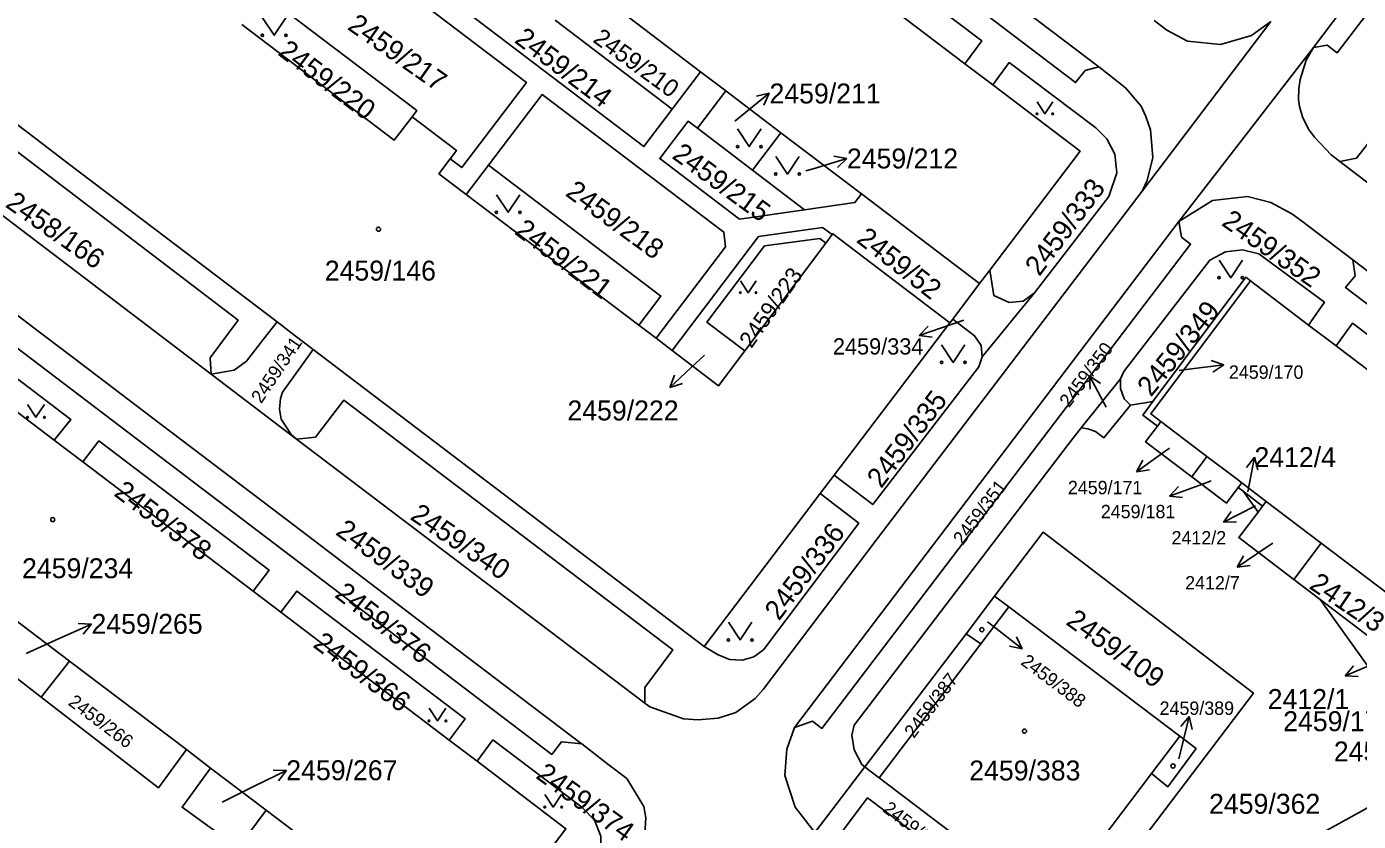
# Model space of a CAD drawing. Extents: x -606208 to -605570, y -1157873 to -1157573.
# Drawn here: x -605870.3 to -605756.7, y -1157700.9 to -1157633.1 of the extents above; entities that cross this region are included whole.
import ezdxf

# ---------------------------------------------------------------- set-up
doc = ezdxf.new("R2010")
doc.units = 0
doc.layers.add('Vrstva 62', color=7, linetype='Continuous')

msp = doc.modelspace()

# ---------------------------------------------------------------- linework, layer by layer
at = {"layer": 'Vrstva 62'}
for p, q in [((-605746.58, -1157616.44), (-605760.58, -1157634.9)), ((-605790.3, -1157636.28), (-605804.68, -1157625.36)), ((-605822.81, -1157629.39), (-605812.84, -1157636.96)), ((-605825.22, -1157632.57), (-605815.25, -1157640.15)), ((-605775.19, -1157647.15), (-605764.22, -1157632.67)), ((-605760.58, -1157634.9), (-605772.05, -1157649.74)), ((-605812.84, -1157636.96), (-605815.25, -1157640.15)), ((-605810.69, -1157638.6), (-605812.84, -1157636.96)), ((-605787.92, -1157638.08), (-605790.3, -1157636.28)), ((-605813.1, -1157641.78), (-605810.69, -1157638.6)), ((-605810.69, -1157638.6), (-605805.99, -1157642.16)), ((-605809.31, -1157640.69), (-605806.98, -1157638.8)), ((-605806.98, -1157638.8), (-605808.07, -1157639.04)), ((-605806.98, -1157638.8), (-605807.44, -1157639.82)), ((-605883.72, -1157640.58), (-605854.57, -1157662.74)), ((-605809.92, -1157641.18), (-605809.31, -1157640.69)), ((-605813.1, -1157641.78), (-605808.4, -1157645.35)), ((-605808.4, -1157645.35), (-605805.99, -1157642.16)), ((-605805.99, -1157642.16), (-605799.12, -1157647.38)), ((-605800.36, -1157644.35), (-605801.46, -1157644.17)), ((-605832.81, -1157647.44), (-605830.91, -1157644.93)), ((-605808.4, -1157645.35), (-605803.96, -1157648.73)), ((-605803.85, -1157645.42), (-605803.23, -1157645.23)), ((-605803.23, -1157645.23), (-605800.36, -1157644.35)), ((-605800.36, -1157644.35), (-605801.17, -1157645.12)), ((-605818.1, -1157658.58), (-605832.81, -1157647.44)), ((-605789.04, -1157655.03), (-605799.12, -1157647.38)), ((-605772.05, -1157649.74), (-605804.82, -1157692.87)), ((-605801.62, -1157650.85), (-605802.16, -1157651.57)), ((-605802.16, -1157651.57), (-605809.07, -1157660.76)), ((-605789.04, -1157655.03), (-605788.16, -1157653.87)), ((-605791.34, -1157658.06), (-605789.04, -1157655.03)), ((-605761, -1157658.57), (-605765.95, -1157654.78)), ((-605784.37, -1157655.81), (-605788.82, -1157661.28)), ((-605867.94, -1157668.37), (-605882.28, -1157657.48)), ((-605816.63, -1157659.69), (-605818.1, -1157658.58)), ((-605801.44, -1157671.35), (-605791.57, -1157658.36)), ((-605791.37, -1157658.47), (-605794.21, -1157659.45)), ((-605794.21, -1157659.45), (-605793.42, -1157658.65)), ((-605791.57, -1157658.36), (-605791.34, -1157658.06)), ((-605790.39, -1157658.14), (-605791.37, -1157658.47)), ((-605758.65, -1157660.32), (-605761, -1157658.57)), ((-605816.63, -1157659.69), (-605815.27, -1157660.72)), ((-605794.21, -1157659.45), (-605793.1, -1157659.59)), ((-605845.86, -1157660.64), (-605812.52, -1157685.95)), ((-605812.5, -1157661.13), (-605813.25, -1157661.82)), ((-605813.25, -1157661.82), (-605815.45, -1157663.87)), ((-605772.03, -1157662.43), (-605771.21, -1157662.32)), ((-605771.21, -1157662.32), (-605768.23, -1157661.95)), ((-605768.23, -1157661.95), (-605769.29, -1157661.58)), ((-605768.23, -1157661.95), (-605769.16, -1157662.57)), ((-605854.57, -1157662.74), (-605847.28, -1157668.28)), ((-605815.45, -1157663.87), (-605815.05, -1157662.82)), ((-605777.03, -1157663.14), (-605780.39, -1157667.33)), ((-605778.25, -1157665.55), (-605779.66, -1157662.9)), ((-605779.66, -1157662.9), (-605778.75, -1157663.55)), ((-605779.66, -1157662.9), (-605779.63, -1157664.02)), ((-605815.45, -1157663.87), (-605814.37, -1157663.55)), ((-605776.18, -1157665.39), (-605774.28, -1157665.09)), ((-605773.88, -1157667.18), (-605773.58, -1157666.78)), ((-605773.58, -1157666.78), (-605769.66, -1157669.76)), ((-605865.51, -1157670.21), (-605867.94, -1157668.37)), ((-605847.28, -1157668.28), (-605817.58, -1157690.8)), ((-605772.85, -1157669.04), (-605773.23, -1157669.32)), ((-605850.97, -1157681.25), (-605865.51, -1157670.21)), ((-605773.23, -1157669.32), (-605775.66, -1157671.08)), ((-605775.66, -1157671.08), (-605775.14, -1157670.09)), ((-605770.96, -1157671.49), (-605769.66, -1157669.76)), ((-605765.61, -1157669.82), (-605766.29, -1157670.71)), ((-605766.18, -1157672.77), (-605765.61, -1157669.82)), ((-605765.61, -1157669.82), (-605765.31, -1157670.9)), ((-605802.63, -1157672.93), (-605801.44, -1157671.35)), ((-605775.66, -1157671.08), (-605774.55, -1157670.9)), ((-605770.03, -1157672.11), (-605772.85, -1157673.14)), ((-605772.85, -1157673.14), (-605772.08, -1157672.32)), ((-605769.29, -1157671.84), (-605770.03, -1157672.11)), ((-605766.69, -1157672.01), (-605766.99, -1157672.41)), ((-605766.99, -1157672.41), (-605766.57, -1157672.73)), ((-605766.69, -1157672.01), (-605764.61, -1157673.59)), ((-605812.52, -1157685.95), (-605802.63, -1157672.93)), ((-605772.85, -1157673.14), (-605771.74, -1157673.26)), ((-605766.57, -1157672.73), (-605765.3, -1157674.51)), ((-605764.91, -1157673.99), (-605766.57, -1157672.73)), ((-605764.91, -1157673.99), (-605764.61, -1157673.59)), ((-605764.61, -1157673.59), (-605759.91, -1157677.16)), ((-605765.58, -1157673.99), (-605768.25, -1157675.35)), ((-605768.25, -1157675.35), (-605767.59, -1157674.45)), ((-605765.52, -1157673.96), (-605765.58, -1157673.99)), ((-605765.3, -1157674.51), (-605764.91, -1157673.99)), ((-605768.25, -1157675.35), (-605767.13, -1157675.34)), ((-605764.6, -1157677.52), (-605767.09, -1157679.2)), ((-605767.09, -1157679.2), (-605766.54, -1157678.22)), ((-605764.05, -1157677.15), (-605764.6, -1157677.52)), ((-605759.91, -1157677.16), (-605762.25, -1157680.24)), ((-605759.91, -1157677.16), (-605752.43, -1157682.83)), ((-605767.09, -1157679.2), (-605765.98, -1157679.05)), ((-605762.25, -1157680.24), (-605760, -1157681.95)), ((-605848.61, -1157683.04), (-605850.97, -1157681.25)), ((-605790.19, -1157684.87), (-605787.77, -1157681.67)), ((-605787.77, -1157681.67), (-605786.56, -1157682.59)), ((-605786.56, -1157682.59), (-605788.94, -1157685.73)), ((-605786.56, -1157682.59), (-605771.98, -1157693.61)), ((-605871.39, -1157683.59), (-605866.63, -1157687.2)), ((-605834.26, -1157693.94), (-605848.61, -1157683.04)), ((-605788.37, -1157683.85), (-605787.77, -1157684.31)), ((-605867.51, -1157685.27), (-605864.77, -1157684.05)), ((-605864.77, -1157684.05), (-605865.89, -1157684)), ((-605864.77, -1157684.05), (-605865.48, -1157684.91)), ((-605798.82, -1157696.23), (-605790.19, -1157684.87)), ((-605788.94, -1157685.73), (-605790.19, -1157684.87)), ((-605787.77, -1157684.31), (-605785.41, -1157686.16)), ((-605870.35, -1157686.55), (-605867.51, -1157685.27)), ((-605788.94, -1157685.73), (-605797.62, -1157697.15)), ((-605785.41, -1157686.16), (-605786.5, -1157685.94)), ((-605785.41, -1157686.16), (-605785.89, -1157685.15)), ((-605869.06, -1157690.28), (-605866.63, -1157687.2)), ((-605866.63, -1157687.2), (-605856.68, -1157694.75)), ((-605755.11, -1157687.29), (-605757.87, -1157688.46)), ((-605757.87, -1157688.46), (-605757.15, -1157687.61)), ((-605757.87, -1157688.46), (-605756.76, -1157688.53)), ((-605771.9, -1157694.85), (-605771.17, -1157691.94)), ((-605771.17, -1157691.94), (-605771.9, -1157692.79)), ((-605771.17, -1157691.94), (-605770.93, -1157693.03)), ((-605831.89, -1157695.74), (-605834.26, -1157693.94)), ((-605774.39, -1157696.8), (-605771.98, -1157693.61)), ((-605854.61, -1157696.32), (-605856.68, -1157694.75)), ((-605772.07, -1157695.53), (-605771.9, -1157694.85)), ((-605854.61, -1157696.32), (-605849.88, -1157699.91)), ((-605798.82, -1157696.23), (-605803.08, -1157701.83)), ((-605850.85, -1157697.84), (-605848.15, -1157696.52)), ((-605848.15, -1157696.52), (-605849.27, -1157696.51)), ((-605848.15, -1157696.52), (-605848.83, -1157697.41)), ((-605788.23, -1157704.27), (-605797.62, -1157697.15)), ((-605853.64, -1157699.22), (-605850.85, -1157697.84)), ((-605852.27, -1157703.13), (-605849.88, -1157699.91))]:
    msp.add_line(p, q, dxfattribs=at)
for points in [[(-605778.88, -1157636.54), (-605780.04, -1157636.85), (-605780.86, -1157637.89), (-605819.82, -1157608.27), (-605840.4, -1157592.63), (-605839.55, -1157591.51), (-605839.57, -1157590.41)], [(-605839.57, -1157590.41), (-605835.8, -1157593.29), (-605832.45, -1157595.85), (-605828.25, -1157599.04), (-605822.26, -1157603.58), (-605815.67, -1157608.59), (-605806.61, -1157615.48), (-605805.91, -1157616.02), (-605794.65, -1157624.58), (-605782.86, -1157633.54), (-605778.88, -1157636.54)], [(-605728.14, -1157592.1), (-605727.92, -1157593.36), (-605727.16, -1157593.95), (-605730.39, -1157598.18), (-605736.65, -1157606.46), (-605742.95, -1157614.78), (-605749.21, -1157623.05), (-605755.41, -1157631.22), (-605758.56, -1157635.36), (-605759.42, -1157634.71), (-605760.58, -1157634.9)], [(-605804.68, -1157625.36), (-605803.23, -1157623.47), (-605788.86, -1157634.32), (-605790.3, -1157636.28)], [(-605850.02, -1157630.42), (-605845.44, -1157624.39), (-605827.68, -1157637.87), (-605833.2, -1157645.14), (-605834.19, -1157644.39)], [(-605815.25, -1157640.15), (-605817.67, -1157643.34), (-605833.24, -1157631.52), (-605830.83, -1157628.33), (-605829.93, -1157629.01)], [(-605850.02, -1157630.42), (-605837.04, -1157640.28), (-605837.43, -1157640.8)], [(-605850.19, -1157632.36), (-605849.19, -1157633.86), (-605848.19, -1157632.36)], [(-605764.22, -1157632.67), (-605765.86, -1157633.89), (-605768.49, -1157634.64), (-605771.31, -1157634.35), (-605773.09, -1157633.43), (-605774.17, -1157632.61)], [(-605837.43, -1157640.8), (-605838.95, -1157642.79), (-605851.94, -1157632.94)], [(-605879.86, -1157634.83), (-605869.57, -1157642.64), (-605866.75, -1157644.79), (-605858.45, -1157651.08), (-605848.95, -1157658.29)], [(-605758.34, -1157644.62), (-605759.06, -1157644.04), (-605760.49, -1157642.55), (-605761.01, -1157641.86), (-605761.52, -1157640.82), (-605761.77, -1157639.92), (-605761.85, -1157639.32), (-605761.83, -1157638.39), (-605761.7, -1157637.62), (-605761.2, -1157635.98), (-605760.58, -1157634.9)], [(-605787.92, -1157638.08), (-605786.51, -1157636.18), (-605779.14, -1157641.75), (-605778.2, -1157642.69), (-605777.51, -1157643.99), (-605777.33, -1157645.58), (-605778.03, -1157647.59), (-605784.37, -1157655.81)], [(-605883.72, -1157640.58), (-605882.51, -1157640.16), (-605880.08, -1157636.95), (-605852.25, -1157658.15), (-605854.64, -1157661.35), (-605854.57, -1157662.74)], [(-605778.88, -1157636.54), (-605777.98, -1157637.26), (-605776.61, -1157638.34), (-605775.27, -1157639.89), (-605774.86, -1157640.78), (-605774.48, -1157641.92), (-605774.27, -1157644.28), (-605774.77, -1157646.25), (-605775.19, -1157647.15)], [(-605788.16, -1157653.87), (-605780.47, -1157643.74), (-605787.92, -1157638.08)], [(-605830.91, -1157644.93), (-605826.33, -1157638.9), (-605810.86, -1157650.64), (-605810.7, -1157651.89), (-605816.63, -1157659.69)], [(-605784.15, -1157639.54), (-605783.48, -1157640.55), (-605782.81, -1157639.54)], [(-605834.19, -1157644.39), (-605833.65, -1157643.67), (-605837.43, -1157640.8)], [(-605803.96, -1157648.73), (-605809.51, -1157649.54), (-605816.32, -1157644.37), (-605813.9, -1157641.18), (-605813.1, -1157641.78)], [(-605809.68, -1157641.84), (-605808.68, -1157643.34), (-605807.68, -1157641.84)], [(-605758.34, -1157644.62), (-605756.9, -1157644.34), (-605754.41, -1157641.15), (-605742.86, -1157650.08), (-605733.69, -1157657.06), (-605723.64, -1157664.65), (-605726.01, -1157667.78), (-605725.81, -1157669.27)], [(-605806.42, -1157644.19), (-605805.42, -1157645.69), (-605804.42, -1157644.19)], [(-605834.19, -1157644.39), (-605835.16, -1157645.66), (-605832.81, -1157647.44)], [(-605830.91, -1157644.93), (-605816.21, -1157656.09), (-605818.1, -1157658.58)], [(-605725.81, -1157669.27), (-605735.95, -1157661.62), (-605747.07, -1157653.21), (-605758.34, -1157644.62)], [(-605830.24, -1157647.45), (-605829.24, -1157648.95), (-605828.24, -1157647.45)], [(-605817.58, -1157690.8), (-605817.17, -1157691.11), (-605814.3, -1157692.13), (-605813.03, -1157692.2), (-605811.33, -1157692.07), (-605809.82, -1157691.58), (-605808.19, -1157690.38), (-605807.51, -1157689.63), (-605797.85, -1157676.91), (-605775.19, -1157647.15)], [(-605799.12, -1157647.38), (-605799.68, -1157648.12), (-605803.96, -1157648.73)], [(-605772.05, -1157649.74), (-605769.19, -1157647.94), (-605766.19, -1157647.59), (-605764.2, -1157648.1), (-605762.42, -1157649.07), (-605761.6, -1157649.67), (-605757.23, -1157653.01)], [(-605822.96, -1157694.27), (-605824.7, -1157694.08), (-605825.52, -1157695.16), (-605883.17, -1157651.37), (-605882.4, -1157650.28), (-605882.77, -1157648.83)], [(-605822.96, -1157694.27), (-605823.13, -1157694.14), (-605837.5, -1157683.23), (-605847.55, -1157675.59), (-605851.06, -1157672.93), (-605858.82, -1157667.03), (-605867.01, -1157660.81), (-605869.19, -1157659.16), (-605877.11, -1157653.13), (-605879.78, -1157651.1), (-605882.77, -1157648.83)], [(-605804.82, -1157692.87), (-605803.3, -1157692.33), (-605802.49, -1157692.94), (-605771.05, -1157651.66), (-605771.84, -1157651.06), (-605772.05, -1157649.74)], [(-605815.27, -1157660.72), (-605807.91, -1157651.02), (-605802.43, -1157650.24), (-605801.62, -1157650.85)], [(-605801.62, -1157650.85), (-605801.56, -1157650.77), (-605791.57, -1157658.36)], [(-605809.07, -1157660.76), (-605812.31, -1157658.3), (-605807.38, -1157651.82), (-605802.68, -1157651.18), (-605802.16, -1157651.57)], [(-605761, -1157658.57), (-605759.64, -1157656.61), (-605765.24, -1157652.49), (-605766.64, -1157652.15), (-605768.07, -1157652.33), (-605769.42, -1157653.04), (-605776.74, -1157662.52), (-605777.03, -1157663.14)], [(-605768.63, -1157653.02), (-605767.63, -1157654.52), (-605766.63, -1157653.02)], [(-605757.23, -1157653.01), (-605757.01, -1157654.35), (-605757.84, -1157655.37), (-605722.72, -1157682), (-605721.89, -1157680.95), (-605720.66, -1157680.78)], [(-605757.23, -1157653.01), (-605752.59, -1157656.53), (-605749.48, -1157658.89), (-605740.38, -1157665.78), (-605731.2, -1157672.77), (-605729.85, -1157673.79), (-605728.35, -1157674.93), (-605720.66, -1157680.78)], [(-605788.16, -1157653.87), (-605787.84, -1157656.03), (-605786.51, -1157656.64), (-605785.33, -1157656.53), (-605784.37, -1157655.81)], [(-605809.44, -1157654.79), (-605808.77, -1157655.8), (-605808.1, -1157654.79)], [(-605765.95, -1157654.78), (-605774.44, -1157666.13), (-605773.58, -1157666.78)], [(-605765.95, -1157654.78), (-605766.35, -1157654.48), (-605774.28, -1157665.09)], [(-605882.28, -1157657.48), (-605880.89, -1157655.7), (-605866.53, -1157666.6), (-605867.94, -1157668.37)], [(-605854.57, -1157662.74), (-605852.61, -1157662.41), (-605851.56, -1157661.63), (-605850.1, -1157659.76), (-605848.95, -1157658.29)], [(-605848.95, -1157658.29), (-605847.4, -1157659.47), (-605845.86, -1157660.64)], [(-605788.82, -1157661.28), (-605788.91, -1157660.3), (-605789.47, -1157659.47), (-605791.34, -1157658.06)], [(-605746.64, -1157669.44), (-605745.21, -1157667.49), (-605757.24, -1157658.39), (-605758.65, -1157660.32)], [(-605845.86, -1157660.64), (-605846.94, -1157662.14), (-605848.47, -1157664.27), (-605848.65, -1157664.82), (-605848.75, -1157665.74), (-605848.59, -1157666.57), (-605847.73, -1157667.88), (-605847.28, -1157668.28)], [(-605809.07, -1157660.76), (-605811.3, -1157663.73), (-605815.27, -1157660.72)], [(-605792.29, -1157660.25), (-605791.29, -1157661.75), (-605790.29, -1157660.25)], [(-605755.68, -1157662.57), (-605758.51, -1157660.43), (-605758.65, -1157660.32)], [(-605788.82, -1157661.28), (-605789.1, -1157662.11), (-605798.15, -1157673.87), (-605801.44, -1157671.35)], [(-605777.03, -1157663.14), (-605777.03, -1157663.98), (-605776.71, -1157664.84), (-605776.18, -1157665.39)], [(-605870.22, -1157665.34), (-605869.5, -1157666.42), (-605868.78, -1157665.34)], [(-605847.28, -1157668.28), (-605845.67, -1157668.12), (-605843.24, -1157664.96), (-605815.19, -1157686.25), (-605817.59, -1157689.47), (-605817.58, -1157690.8)], [(-605780.39, -1157667.33), (-605779.83, -1157667.41), (-605779.17, -1157667.63), (-605778.45, -1157668.17), (-605776.18, -1157665.39)], [(-605774.28, -1157665.09), (-605775.14, -1157666.23), (-605773.88, -1157667.18)], [(-605798.82, -1157696.23), (-605799.09, -1157696.01), (-605799.75, -1157694.78), (-605799.94, -1157693.51), (-605799.75, -1157692.67), (-605781.5, -1157668.74), (-605780.39, -1157667.33)], [(-605773.88, -1157667.18), (-605774.89, -1157668.51), (-605770.96, -1157671.49)], [(-605865.51, -1157670.21), (-605864.13, -1157668.43), (-605849.61, -1157679.46), (-605850.97, -1157681.25)], [(-605769.66, -1157669.76), (-605767.54, -1157671.36), (-605766.69, -1157672.01)], [(-605770.96, -1157671.49), (-605768, -1157673.74), (-605766.99, -1157672.41)], [(-605802.63, -1157672.93), (-605799.35, -1157675.45), (-605807.47, -1157686.24), (-605808.3, -1157686.84), (-605809.28, -1157687.13), (-605810.38, -1157687.06), (-605811.38, -1157686.65), (-605812.52, -1157685.95)], [(-605765.3, -1157674.51), (-605766.95, -1157676.67), (-605762.25, -1157680.24)], [(-605787.77, -1157681.67), (-605783.63, -1157676.22), (-605765.7, -1157689.93), (-605783.71, -1157713.66)], [(-605848.61, -1157683.04), (-605847.26, -1157681.24), (-605832.92, -1157692.12), (-605834.26, -1157693.94)], [(-605760, -1157681.95), (-605754.81, -1157689.23), (-605752.31, -1157687.79)], [(-605760, -1157681.95), (-605754.77, -1157685.92), (-605752.73, -1157683.23)], [(-605869.06, -1157690.28), (-605873.69, -1157686.7), (-605871.39, -1157683.59)], [(-605810.46, -1157683.9), (-605809.46, -1157685.4), (-605808.46, -1157683.9)], [(-605856.68, -1157694.75), (-605859.06, -1157698), (-605869.06, -1157690.28)], [(-605835.99, -1157691.22), (-605835.27, -1157692.3), (-605834.55, -1157691.22)], [(-605803.08, -1157701.83), (-605804.76, -1157699.67), (-605805.66, -1157696.95), (-605805.49, -1157694.72), (-605804.82, -1157692.87)], [(-605831.89, -1157695.74), (-605830.54, -1157693.93), (-605822.95, -1157699.67), (-605821.88, -1157700.77), (-605821.33, -1157702.13), (-605821.3, -1157703.54), (-605821.87, -1157705.02), (-605827.73, -1157712.76), (-605828.43, -1157713.4), (-605829.39, -1157713.68)], [(-605744.75, -1157693.52), (-605778.05, -1157711.9), (-605782.37, -1157714.52)], [(-605771.98, -1157693.61), (-605770.59, -1157694.66), (-605772.99, -1157697.91), (-605774.39, -1157696.8)], [(-605836.37, -1157727.55), (-605817.59, -1157701.91), (-605817.5, -1157700.57), (-605817.68, -1157699.61), (-605819.13, -1157697.22), (-605820.74, -1157695.98), (-605822.96, -1157694.27)], [(-605852.27, -1157703.13), (-605857.04, -1157699.67), (-605854.61, -1157696.32)], [(-605830.28, -1157709.35), (-605824.31, -1157701.49), (-605831.89, -1157695.74)], [(-605797.62, -1157697.15), (-605798.51, -1157696.48), (-605798.82, -1157696.23)], [(-605774.39, -1157696.8), (-605783.02, -1157708.22), (-605788.23, -1157704.27)], [(-605826.12, -1157698.57), (-605825.4, -1157699.65), (-605824.68, -1157698.57)], [(-605803.08, -1157701.83), (-605800.86, -1157701.84), (-605798.6, -1157698.86), (-605790.97, -1157704.62), (-605793.31, -1157707.75), (-605792.9, -1157709.62)], [(-605849.88, -1157699.91), (-605842.9, -1157705.21), (-605843.43, -1157705.91)]]:
    msp.add_lwpolyline(points, dxfattribs=at)
for centre, radius in [((-605850.19, -1157633.86), 0.1), ((-605848.19, -1157633.86), 0.1), ((-605784.15, -1157640.55), 0.067), ((-605782.81, -1157640.55), 0.067), ((-605809.68, -1157643.34), 0.1), ((-605807.68, -1157643.34), 0.1), ((-605806.42, -1157645.69), 0.1), ((-605804.42, -1157645.69), 0.1), ((-605830.24, -1157648.95), 0.1), ((-605828.24, -1157648.95), 0.1), ((-605840.3, -1157650.39), 0.175), ((-605768.63, -1157654.52), 0.1), ((-605766.63, -1157654.52), 0.1), ((-605809.44, -1157655.8), 0.067), ((-605808.1, -1157655.8), 0.067), ((-605792.29, -1157661.75), 0.1), ((-605790.29, -1157661.75), 0.1), ((-605870.22, -1157666.42), 0.072), ((-605868.78, -1157666.42), 0.072), ((-605868.07, -1157675.14), 0.175), ((-605788.85, -1157684.53), 0.175), ((-605810.46, -1157685.4), 0.1), ((-605808.46, -1157685.4), 0.1), ((-605835.99, -1157692.3), 0.072), ((-605834.55, -1157692.3), 0.072), ((-605785.22, -1157693.18), 0.175), ((-605772.55, -1157696.15), 0.175), ((-605826.12, -1157699.65), 0.072), ((-605824.68, -1157699.65), 0.072)]:
    msp.add_circle(centre, radius, dxfattribs=at)

# ---------------------------------------------------------------- texts
for s, height, rotation, p in [('2459/217', 1.7, 325, (-605843.03, -1157633.29)), ('2459/214', 1.7, 323, (-605828.79, -1157634.41)), ('2459/210', 1.488, 324, (-605822.1, -1157634.37)), ('2459/220', 1.7, 323, (-605848.96, -1157635.47)), ('2459/215', 1.7, 324, (-605815.36, -1157644.28)), ('2459/218', 1.7, 324, (-605824.45, -1157647.47)), ('2459/333', 1.7, 53, (-605783.95, -1157654.47)), ('2458/166', 1.7, 325, (-605872.2, -1157648.43)), ('2459/221', 1.7, 323, (-605828.78, -1157650.73)), ('2459/352', 1.7, 325, (-605768.5, -1157650)), ('2459/52', 1.7, 322, (-605799.64, -1157651.42)), ('2459/223', 1.384, 55, (-605808.5, -1157660.61)), ('2459/349', 1.7, 51, (-605774.43, -1157664.75)), ('2459/341', 1.139, 56, (-605850.3, -1157665.32)), ('2459/350', 1.139, 53, (-605781.42, -1157665.66)), ('2459/335', 1.7, 53, (-605797.43, -1157672.55)), ('2459/378', 1.7, 323, (-605862.94, -1157673.04)), ('2459/351', 1.139, 53, (-605790.49, -1157677.39)), ('2459/340', 1.7, 326, (-605837.69, -1157675.06)), ('2459/339', 1.7, 324, (-605844.04, -1157676.36)), ('2459/336', 1.7, 53, (-605806.15, -1157683.84)), ('2412/3', 1.7, 326, (-605761.03, -1157680.95)), ('2459/376', 1.7, 322, (-605844.12, -1157681.68)), ('2459/109', 1.7, 324, (-605781.77, -1157684.02)), ('2459/366', 1.7, 323, (-605845.97, -1157685.94)), ('2459/388', 1.139, 323, (-605785.61, -1157687.43)), ('2459/387', 1.139, 53, (-605794.65, -1157693.85)), ('2459/266', 1.139, 323, (-605866.83, -1157690.88)), ('2459/374', 1.7, 324, (-605826.97, -1157697.12)), ('2459/353', 1.139, 322, (-605797.38, -1157699.96))]:
    msp.add_text(s, height=height, rotation=rotation, dxfattribs=at).set_placement(p)
for s, height, p in [('2459/211', 1.7, (-605806.96, -1157639.67)), ('2459/212', 1.7, (-605800.36, -1157645.21)), ('2459/146', 1.7, (-605844.88, -1157654.77)), ('2459/334', 1.383, (-605801.55, -1157661.07)), ('2459/170', 1.139, (-605767.79, -1157663.14)), ('2459/222', 1.7, (-605824.19, -1157666.69)), ('2412/4', 1.7, (-605765.61, -1157670.67)), ('2459/171', 1.139, (-605781.52, -1157672.98)), ('2459/181', 1.139, (-605778.71, -1157675.03)), ('2412/2', 1.139, (-605772.68, -1157677.26)), ('2459/234', 1.7, (-605870.69, -1157680.14)), ('2412/7', 1.139, (-605771.52, -1157681.1)), ('2459/265', 1.7, (-605864.77, -1157684.88)), ('2412/1', 1.7, (-605764.48, -1157691.29)), ('2459/389', 1.139, (-605773.7, -1157691.79)), ('2459/176', 1.7, (-605763.16, -1157693.18)), ('2459/178', 1.7, (-605758.84, -1157695.76)), ('2459/267', 1.7, (-605848.16, -1157697.36)), ('2459/383', 1.7, (-605789.93, -1157697.38)), ('2459/362', 1.7, (-605769.48, -1157700.22))]:
    msp.add_text(s, height=height, dxfattribs=at).set_placement(p)

doc.saveas('drawing.dxf')
